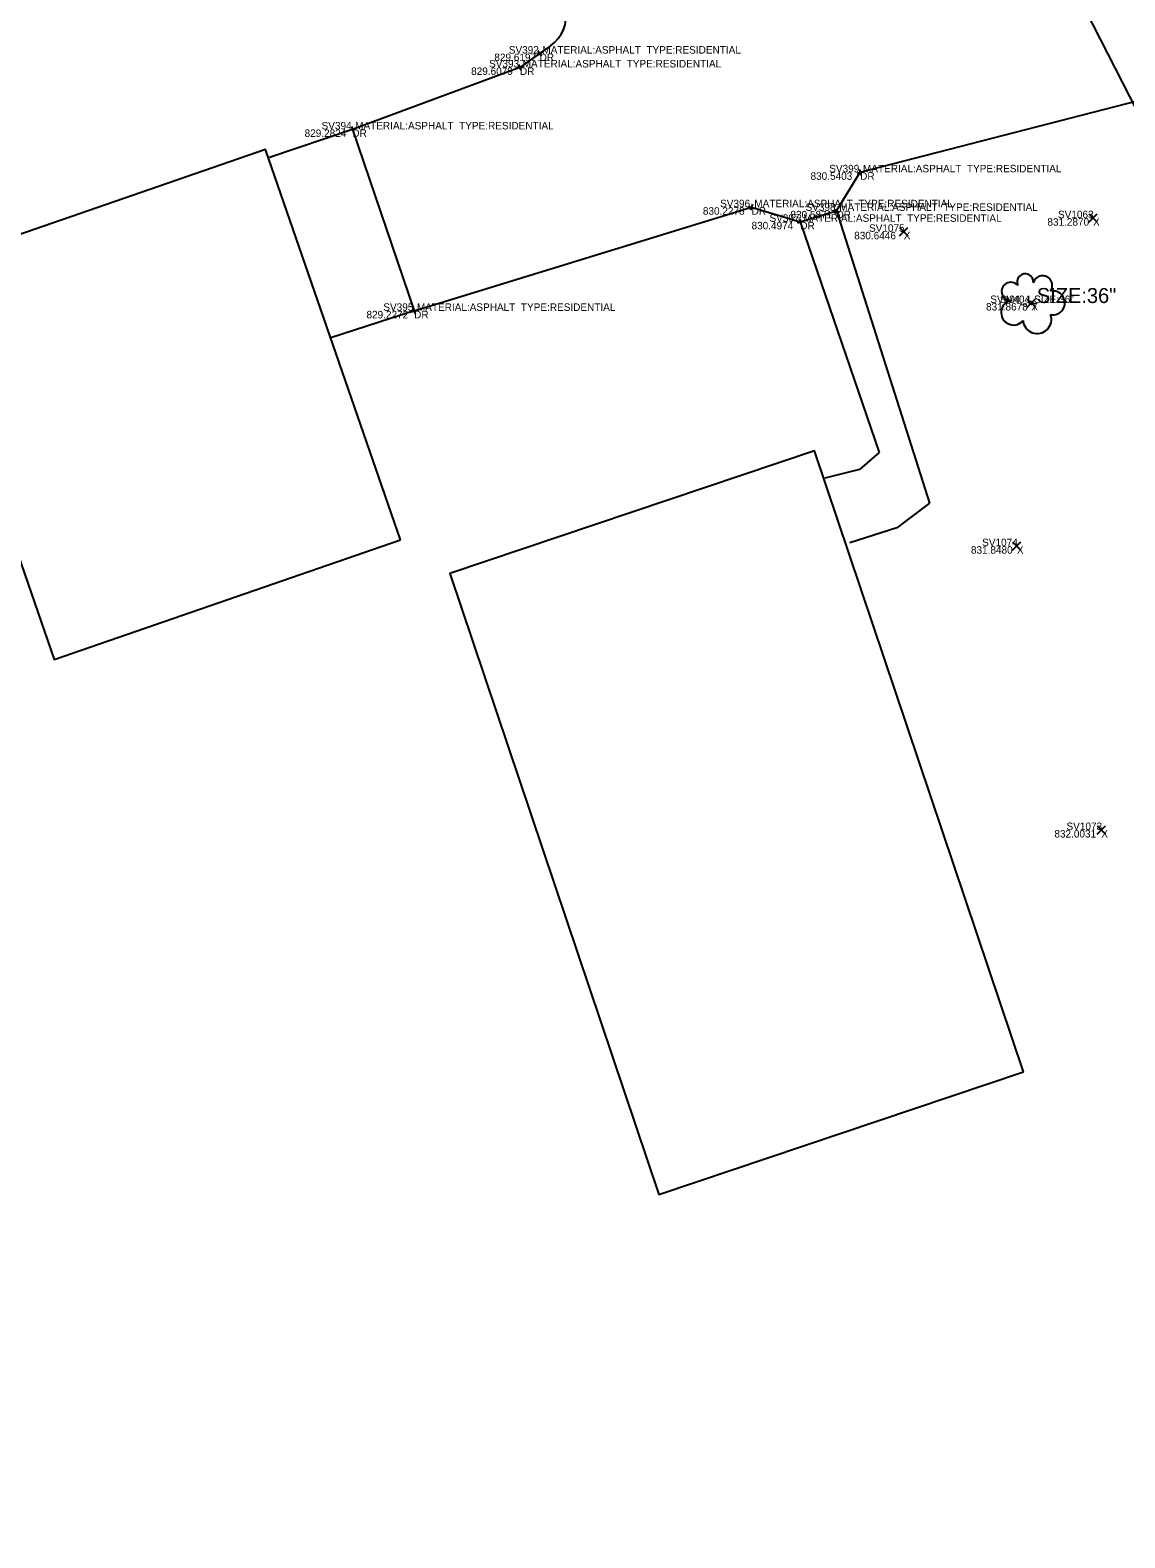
# Model space of a CAD drawing. Extents: x 1715717 to 1717046, y 393954 to 396000.
# Drawn here: x 1716038.3 to 1716126.1, y 394753 to 394873.9 of the extents above; entities that cross this region are included whole.
import ezdxf

# ---------------------------------------------------------------- set-up
doc = ezdxf.new("R2010")
doc.units = 0
for name, color, linetype in [('BD_X_Building', 7, 'Continuous'), ('PV_X_Driveway', 7, 'Continuous'), ('PV_X_Parking_Lot', 7, 'Continuous'), ('PV_X_Walk', 7, 'Continuous'), ('SV_X_Random_Point', 7, 'Continuous'), ('SV_X_Shot_Marker', 7, 'Continuous'), ('SV_X_Text_Comment', 7, 'Continuous'), ('SV_X_Text_Description', 7, 'Continuous'), ('SV_X_Text_Elevation', 7, 'Continuous'), ('SV_X_Text_Name', 7, 'Continuous'), ('UT_X_Overhead_Telecom', 7, 'Continuous'), ('VG_X_Cells', 7, 'Continuous'), ('VG_X_Text', 7, 'Continuous')]:
    doc.layers.add(name, color=color, linetype=linetype)

msp = doc.modelspace()

# ---------------------------------------------------------------- linework, layer by layer
at = {"layer": 'BD_X_Building'}
for points in [[(1716068, 394833.07), (1716057.18, 394864.36), (1716029.42, 394854.77), (1716040.25, 394823.47)], [(1716117.95, 394790.4), (1716101.19, 394840.19), (1716071.95, 394830.35), (1716088.71, 394780.56)]]:
    msp.add_lwpolyline(points, close=True, dxfattribs=at)
at = {"layer": 'PV_X_Driveway'}
for p, q in [((1716080.03, 394872.67), (1716079.16, 394872.05)), ((1716077.58, 394870.94), (1716064.15, 394865.97)), ((1716079.16, 394872.05), (1716077.58, 394870.94)), ((1716104.86, 394862.53), (1716131.35, 394869.38)), ((1716064.15, 394865.97), (1716069.1, 394851.42)), ((1716102.96, 394859.44), (1716104.86, 394862.53)), ((1716069.1, 394851.42), (1716096.15, 394859.73)), ((1716096.15, 394859.73), (1716100.06, 394858.56)), ((1716100.06, 394858.56), (1716102.96, 394859.44))]:
    msp.add_line(p, q, dxfattribs=at)
msp.add_arc((1716078.31, 394875.1), 2.98, 305.2491, 10.1308, dxfattribs=at)
at = {"layer": 'PV_X_Parking_Lot'}
for p, q in [((1716064.15, 394865.97), (1716057.5, 394863.73)), ((1716069.1, 394851.42), (1716062.42, 394849.27))]:
    msp.add_line(p, q, dxfattribs=at)
at = {"layer": 'PV_X_Walk'}
for p, q in [((1716102.96, 394859.44), (1716110.43, 394836)), ((1716100.06, 394858.56), (1716106.39, 394840.07)), ((1716106.39, 394840.07), (1716104.8, 394838.71)), ((1716104.8, 394838.71), (1716102.02, 394838.01)), ((1716110.43, 394836), (1716107.79, 394834.02)), ((1716107.79, 394834.02), (1716104.03, 394832.82))]:
    msp.add_line(p, q, dxfattribs=at)
at = {"layer": 'SV_X_Random_Point'}
for p, q in [((1716123.19, 394858.52), (1716123.86, 394859.19)), ((1716123.19, 394859.19), (1716123.86, 394858.52)), ((1716108.02, 394857.43), (1716108.69, 394858.1)), ((1716108.02, 394858.1), (1716108.69, 394857.43)), ((1716118.25, 394851.71), (1716118.91, 394852.38)), ((1716118.25, 394852.38), (1716118.91, 394851.71)), ((1716117.08, 394832.22), (1716117.75, 394832.89)), ((1716117.08, 394832.89), (1716117.75, 394832.22)), ((1716123.85, 394809.45), (1716124.52, 394810.12)), ((1716123.85, 394810.12), (1716124.52, 394809.45))]:
    msp.add_line(p, q, dxfattribs=at)
at = {"layer": 'SV_X_Shot_Marker'}
for p, q in [((1716079.36, 394872.2), (1716078.96, 394871.91)), ((1716079.3, 394871.85), (1716079.02, 394872.26)), ((1716077.82, 394871.03), (1716077.35, 394870.85)), ((1716077.67, 394870.71), (1716077.5, 394871.17)), ((1716077.58, 394870.94), (1716077.58, 394870.94)), ((1716079.16, 394872.05), (1716079.16, 394872.05)), ((1716064.38, 394866.05), (1716063.91, 394865.89)), ((1716064.07, 394866.21), (1716064.23, 394865.74)), ((1716064.15, 394865.97), (1716064.15, 394865.97)), ((1716104.62, 394862.46), (1716105.1, 394862.59)), ((1716104.8, 394862.77), (1716104.92, 394862.29)), ((1716104.86, 394862.53), (1716104.86, 394862.53)), ((1716095.91, 394859.8), (1716096.39, 394859.66)), ((1716096.22, 394859.97), (1716096.07, 394859.49)), ((1716096.15, 394859.73), (1716096.15, 394859.73)), ((1716102.75, 394859.57), (1716103.18, 394859.31)), ((1716102.83, 394859.23), (1716103.1, 394859.66)), ((1716102.96, 394859.44), (1716102.96, 394859.44)), ((1716099.83, 394858.48), (1716100.3, 394858.63)), ((1716099.99, 394858.79), (1716100.14, 394858.32)), ((1716100.06, 394858.56), (1716100.06, 394858.56)), ((1716069.03, 394851.66), (1716069.18, 394851.18)), ((1716068.86, 394851.35), (1716069.34, 394851.5)), ((1716069.1, 394851.42), (1716069.1, 394851.42))]:
    msp.add_line(p, q, dxfattribs=at)
at = {"layer": 'UT_X_Overhead_Telecom'}
msp.add_line((1716209.53, 394705.31), (1716026.85, 395064.48), dxfattribs=at)
at = {"layer": 'VG_X_Cells'}
msp.add_circle((1716118.58, 394852.05), 0.12, dxfattribs=at)
for centre, radius, start, end in [((1716118.09, 394853.73), 0.658, 354.0047, 205.9741), ((1716119.49, 394853.46), 0.776, 323.83, 165.0376), ((1716116.93, 394852.98), 0.735, 39.0625, 279.5412), ((1716120.31, 394852.06), 0.957, 259.1453, 101.4596), ((1716117.15, 394851.27), 0.987, 96.1722, 320.5737), ((1716119.05, 394850.74), 1.14, 184.9476, 19.4572)]:
    msp.add_arc(centre, radius, start, end, dxfattribs=at)

# ---------------------------------------------------------------- texts
at = {"layer": 'SV_X_Text_Comment'}
for s, p in [('DR', (1716077.58, 394870.34)), ('DR', (1716079.16, 394871.45)), ('DR', (1716064.15, 394865.37)), ('DR', (1716104.86, 394861.93)), ('DR', (1716096.15, 394859.13)), ('DR', (1716102.96, 394858.84)), ('X', (1716123.53, 394858.25)), ('DR', (1716100.06, 394857.96)), ('X', (1716108.35, 394857.16)), ('T', (1716118.58, 394851.45)), ('X', (1716118.58, 394851.45)), ('DR', (1716069.1, 394850.82)), ('X', (1716117.42, 394831.95)), ('X', (1716124.19, 394809.19))]:
    msp.add_text(s, height=0.6, dxfattribs=at).set_placement(p)
at = {"layer": 'SV_X_Text_Description'}
for s, p in [(' MATERIAL:ASPHALT  TYPE:RESIDENTIAL ', (1716079.16, 394872.05)), (' MATERIAL:ASPHALT  TYPE:RESIDENTIAL ', (1716077.58, 394870.94)), (' MATERIAL:ASPHALT  TYPE:RESIDENTIAL ', (1716064.15, 394865.97)), (' MATERIAL:ASPHALT  TYPE:RESIDENTIAL ', (1716104.86, 394862.53)), (' MATERIAL:ASPHALT  TYPE:RESIDENTIAL ', (1716096.15, 394859.73)), (' MATERIAL:ASPHALT  TYPE:RESIDENTIAL ', (1716102.96, 394859.44)), (' MATERIAL:ASPHALT  TYPE:RESIDENTIAL ', (1716100.06, 394858.56)), (' MATERIAL:ASPHALT  TYPE:RESIDENTIAL ', (1716069.1, 394851.42)), (' SIZE:36" ', (1716118.58, 394852.05))]:
    msp.add_text(s, height=0.6, dxfattribs=at).set_placement(p)
at = {"layer": 'SV_X_Text_Elevation'}
for s, p in [('829.6079', (1716073.67, 394870.34)), ('829.6197', (1716075.53, 394871.45)), ('829.2824', (1716060.32, 394865.37)), ('830.5403', (1716100.88, 394861.93)), ('830.2278', (1716092.25, 394859.13)), ('830.5871', (1716099.27, 394858.84)), ('831.2870', (1716119.87, 394858.25)), ('830.4974', (1716096.15, 394857.96)), ('830.6446', (1716104.38, 394857.16)), ('831.8678', (1716114.95, 394851.45)), ('831.8678', (1716114.95, 394851.45)), ('829.2272', (1716065.28, 394850.82)), ('831.8480', (1716113.74, 394831.95)), ('832.0031', (1716120.43, 394809.19))]:
    msp.add_text(s, height=0.6, dxfattribs=at).set_placement(p)
at = {"layer": 'SV_X_Text_Name'}
for s, p in [('SV392', (1716076.69, 394872.05)), ('SV393', (1716075.11, 394870.94)), ('SV394', (1716061.68, 394865.97)), ('SV399', (1716102.38, 394862.53)), ('SV396', (1716093.63, 394859.73)), ('SV398', (1716100.48, 394859.44)), ('SV397', (1716097.59, 394858.56)), ('SV1063', (1716120.72, 394858.85)), ('SV1075', (1716105.57, 394857.76)), ('SV395', (1716066.63, 394851.42)), ('SV404_1', (1716115.29, 394852.05)), ('SV404', (1716116.07, 394852.05)), ('SV1074', (1716114.64, 394832.55)), ('SV1073', (1716121.4, 394809.79))]:
    msp.add_text(s, height=0.6, dxfattribs=at).set_placement(p)
at = {"layer": 'VG_X_Text'}
msp.add_text(' SIZE:36" ', height=1.2, dxfattribs=at).set_placement((1716118.58, 394852.05))

doc.saveas('drawing.dxf')
